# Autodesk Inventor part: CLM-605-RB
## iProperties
Company: jsm
Author: XMN5642
Shininess: 5.0
PropertySet Name: _Private Model Information
Created: 2001-04
Part Number: CLM-605-RB
Document SubType Name: Modeling
Designer: XMN5642
Control State: 0
Master: False
Checked Out: False
PropertySet Name: Design Tracking Control
Density: 0.0
Volumn: 0.0
Area: 0.0
PropertySet Name: Model Information
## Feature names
1. Revolution1
2. Chamfer1
3. Chamfer2
